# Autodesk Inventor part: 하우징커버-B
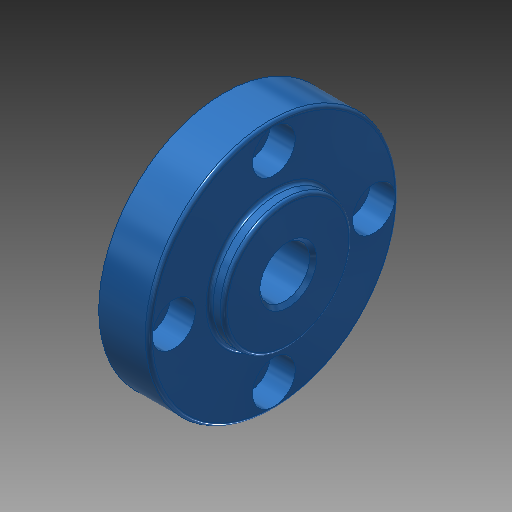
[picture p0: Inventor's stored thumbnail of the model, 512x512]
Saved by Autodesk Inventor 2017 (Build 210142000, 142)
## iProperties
Created: 2018-01
Part Number: 하우징커버-B
Material: 알루미늄 6061
Document SubType Name: Modeling
Designer: mduedu
Density: 2.71 g/cm^3
Mass: 17.2512 g
Surface Area: 32.1467 cm^2
Volume: 6.36575 cm^3
Appearance: 청록색
Author: mduedu
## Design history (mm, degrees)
sketch "스케치1"
  geometry: C1 r 17.5 at (0, 0); 1 further point
  constraints: 1 centre point, 1 coincident
  dimensions: "d0" = 35 diameter of C1
extrude "돌출1" new body sketch "스케치1" distance "d1" = 7; taper "d2" = 0 deg
sketch "스케치2"
  geometry: C1 r 9 at (0, 0); 1 further point
  constraints: 1 centre point, 1 coincident
  dimensions: "d3" = 18 diameter of C1
extrude "돌출2" join sketch "스케치2" distance "d4" = 2; taper "d5" = 0 deg
fillet "모깎기1" dims "d6" = 0.5
fillet "모깎기2" dims "d7" = 0.5
hole "구멍1" diameter "d10" = 7; stored, may be unused: countersink angle "d14" = 90 deg, drill point angle "d16" = 118 deg; dims "d8" = 10, "d9" = 10, "d11" = 6, "d12" = 4, "d13" = 2, "d15" = 8
chamfer "모따기1" distance "d17" = 0.5; stored, may be unused: second distance "d18" = 2, angle "d19" = 45 deg
sketch "스케치3" dims "d21" = 25
  geometry: 6 further points
  constraints: 2 vertical alignment, 1 coincident, 7 other
  dimensions: "d24" = 360 deg dimension on point (0, 0) point (0, 12.5) (derived)
sketch "스케치4"
  geometry: C1 r 17.5 at (0, 0) reference; A1 r 14 centre (0, 0) between (0, 14) and (-14, 0); 2 further points
  constraints: 4 point on circle, 2 horizontal alignment, 2 vertical alignment, 1 centre point, 1 coincident
  dimensions: "d34" = 28 diameter of A1
hole "구멍2" sketch "스케치4" at (-14, 0), (0, -14), (14, 0), (0, 14) diameter "d26" = 3.4; stored, may be unused: countersink angle "d30" = 90 deg, drill point angle "d32" = 0 deg; dims "d27" = 6, "d28" = 6, "d29" = 3.5, "d31" = 8
node "솔리드1"
